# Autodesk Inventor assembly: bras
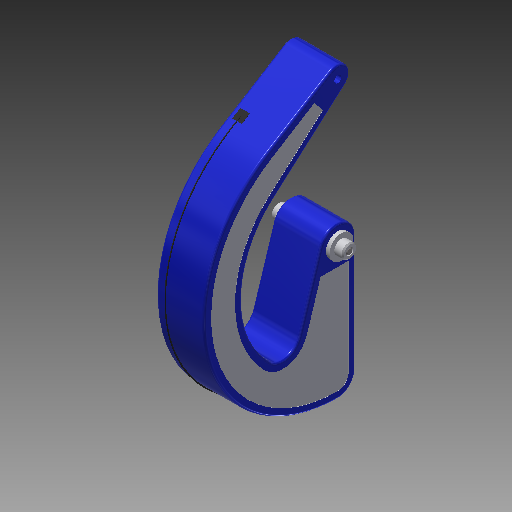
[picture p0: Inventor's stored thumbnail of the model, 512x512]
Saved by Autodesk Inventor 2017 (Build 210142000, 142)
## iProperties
Created: 2013-10
Part Number: bras
Material: Générique
Document SubType Name: Assembly
Designer: Bruno
Sending System: SolidWorks 2013
Last Author: christophe
Last Saved: 2014-02-15
Author: Bruno
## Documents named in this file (6)
- D:\Cours\1-Cours-2018-19\1Ssi\7- EDC-mvt\Haptique-2017\Reel-Inventor\bras.iam
- D:\Cours\1-Cours-2018-19\1Ssi\7- EDC-mvt\Haptique-2017\Reel-Inventor\bras.ipt
- D:\Cours\1-Cours-2018-19\1Ssi\7- EDC-mvt\Haptique-2017\Reel-Inventor\AXE BRAS.ipt
- D:\Cours\1-Cours-2018-19\1Ssi\7- EDC-mvt\Haptique-2017\Reel-Inventor\palier bras.ipt
- D:\Cours\1-Cours-2018-19\1Ssi\7- EDC-mvt\Haptique-2017\Reel-Inventor\Ressort cable.ipt
- D:\Cours\1-Cours-2018-19\1Ssi\7- EDC-mvt\Haptique-2017\Reel-Inventor\FIXATION CABLE.ipt
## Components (6 placed, 5 different names)
1. bras:1
2. AXE BRAS:1
3. palier bras:1
4. palier bras:2
5. Ressort cable:1
6. FIXATION CABLE:1
